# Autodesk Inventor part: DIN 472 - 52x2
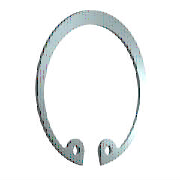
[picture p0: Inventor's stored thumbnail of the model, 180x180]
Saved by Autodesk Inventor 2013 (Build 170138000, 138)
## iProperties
Created: 2012-02
Part Number: DIN 472 - 52x2
Material: Stahl, weich
Description: Sicherungsringe für Bohrungen
Document SubType Name: Modeling
Standard: DIN 472
Designer: Dan
Standards Organization: DIN
Language: de-DE
Size Designation: 52x2
Categories: <MemberInstance><Categories><Category DisplayName="Wellenteile" InternalName="7f7aeb1f-a693-4053-b835-cee3144e0d98" Mnemonic="SHFT"><Category DisplayName="Siche
Density: 7.86 g/cm^3
IsCustomPart: 0
Author: Dan
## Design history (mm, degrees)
node "WorkPlane1"
workplane "Work Plane2"
node "WorkPlane2"
node "WorkPoint1"
node "WorkAxis1"
body "Solid1"
node "Skizze1"
sketch "Skizze2"
  geometry: L1 (6.5, -25.487)-(5.66, -22.033); L2 (9.302, -19.786)-(11.715, -21.834); L3 (-9.302, -19.786)-(-11.715, -21.834); L4 (-6.5, -25.487)-(-5.66, -22.033); L5 (0, 1.233)-(-6.5, -25.487); L6 (0, 1.233)-(6.5, -25.487); A1 r 2.25 centre (7.846, -21.501) between (9.302, -19.786) and (5.66, -22.033); A2 r 24.778 centre (0, 0) between (11.715, -21.834) and (-11.715, -21.834); A3 r 2.25 centre (-7.846, -21.501) between (-5.66, -22.033) and (-9.302, -19.786); A4 r 27.5 centre (0, 1.233) between (6.5, -25.487) and (-6.5, -25.487); 1 further point
  constraints: 12 end point, 8 point on circle, 4 centre point, 4 tangent, 2 point on line, 1 coincident
  dimensions: "d2" = 27.5 radius of A4 (= 0.5 x Diam2); "d4" = 0 horizontal distance of A2.centre L5.start; "d6" = 24.77778 radius of A2 (= 0.5 x msp_dd1); "d8" = 1.23333 distance of A2.centre L5.start (= -0.5 x msp_dd1 + 0.5 x Diam2 - 0.222222 x ParA); "d10" = 6.5 horizontal distance of L4.start L5.start (= 2.6 x Diam5); "d12" = 6.5 horizontal distance of L1.start L5.start (= 2.6 x Diam5); "d14" = 2.25 radius of A1 (= 0.9 x Diam5); "d16" = 2.25 radius of A3 (= 0.9 x Diam5); "d18" = 24.05 distance of A3.centre L5.start (= 1.3 x Diam5 + 0.5 x Diam2 - ParA); "d20" = 24.05 distance of A1.centre L5.start (= 1.3 x Diam5 + 0.5 x Diam2 - ParA); "d22" = 36 deg angle of L1 L2; "d24" = 36 deg angle of L3 L4
extrude "Extrusion1" new body sketch "Skizze2" distance "d25" = 2 (= ParS); taper "d26" = 0 deg
sketch "Skizze3"
  geometry: A1 r 2.25 centre (-7.846, -21.501) between (-5.66, -22.033) and (-9.302, -19.786) reference; 1 further point
  constraints: 1 coincident
hole "Bohrung1" sketch "Skizze3" diameter "d29" = 2.5 (= Diam5); stored, may be unused: countersink angle "d33" = 60 deg, drill point angle "d35" = 118 deg; dims "d30" = 6, "d31" = 4, "d32" = 2, "d34" = 8
sketch "Skizze4"
  geometry: A1 r 2.25 centre (7.846, -21.501) between (9.302, -19.786) and (5.66, -22.033) reference; 1 further point
  constraints: 1 coincident
hole "Bohrung2" sketch "Skizze4" diameter "d36" = 2.5 (= Diam5); stored, may be unused: countersink angle "d40" = 60 deg, drill point angle "d42" = 118 deg; dims "d37" = 6, "d38" = 4, "d39" = 2, "d41" = 8
other parameters: "Diam5" = 2.5 [user parameter; used in 8 equation terms], "ParA" = 6.7 [user parameter; used in 4 equation terms], "b" = 4.7 [user parameter; used in 2 equation terms], "ParS" = 2 [user parameter; used in 2 equation terms], "Diam2" = 55 [user parameter; used in 6 equation terms], "msp_dd1" = 49.55556 (= -b + Diam2 - 0.111111 x ParA) [user parameter; used in 2 equation terms], "msp_pom" = 22.8 (= 0.5 x Diam2 - b) [user parameter], "d0" = -2 (computed from ParS), "d1" = 5.2 (derived), "d3" = 0 (derived), "d5" = 4.22778 (derived), "d7" = 0.28333 (derived), "d9" = 3.12 (derived), "d11" = 3.12 (derived), "d13" = 1.08 (derived), "d15" = 1.08 (derived), "d17" = 3.66 (derived), "d19" = 3.66 (derived), "d21" = 36 deg (derived), "d23" = 36 deg (derived), "d27" = 0, "d28" = 0, "d47" = 0, "d48" = 0, "d49" = 0, "d50" = 0, "TEMPLATE" = 12.345 [user parameter]
